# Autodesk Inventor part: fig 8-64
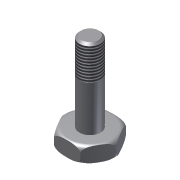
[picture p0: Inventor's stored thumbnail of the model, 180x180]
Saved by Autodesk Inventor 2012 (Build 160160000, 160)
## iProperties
Shininess: 77.0
Length Units: 11269
Angle Units: 11279
Time Units: 11290
Mass Units: 11283
Length Display Precision: 3
Angle Display Precision: 2
Created: 2002-01
Part Number: fig 8-64
Document SubType Name: Modeling
Designer: ***
Density: 1 g/cm^3
Material: Default
Density: 0.0
Volumn: 0.0
Area: 0.0
PropertySet Name: Model Information
Control State: 0
Master: False
Checked Out: False
Author: ***
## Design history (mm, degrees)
sketch "Sketch1"
  geometry: C1 r 25 at (0, 0)
  constraints: 1 centre point
  dimensions: "d0" = 50 diameter of C1
extrude "Extrusion1" new body sketch "Sketch1" distance "d1" = 15; taper "d2" = 0 deg
fillet "Fillet1" dims "d3" = 5
sketch "Sketch2"
  geometry: L1 (25.058, 0)-(12.529, -21.701); L2 (12.529, -21.701)-(-12.529, -21.701); L3 (-12.529, -21.701)-(-25.058, 0); L4 (-25.058, 0)-(-12.529, 21.701); L5 (-12.529, 21.701)-(12.529, 21.701); L6 (12.529, 21.701)-(25.058, 0); 1 further point
  constraints: 12 end point, 11 other
extrude "Extrusion2" sketch "Sketch2" stored distance "d4" = 15; taper "d5" = 0 deg
sketch "Sketch3"
  geometry: C1 r 10.044 at (0, 0); 1 further point
  constraints: 1 centre point, 1 coincident
extrude "Extrusion3" join sketch "Sketch3" distance "d6" = 75; taper "d7" = 0 deg
chamfer "Chamfer1" distance "d8" = 2; stored, may be unused: second distance "d9" = 2, angle "d16" = 45 deg
thread "Thread3" dims "d14" = 30, "d15" = 0
body "Solid1"
